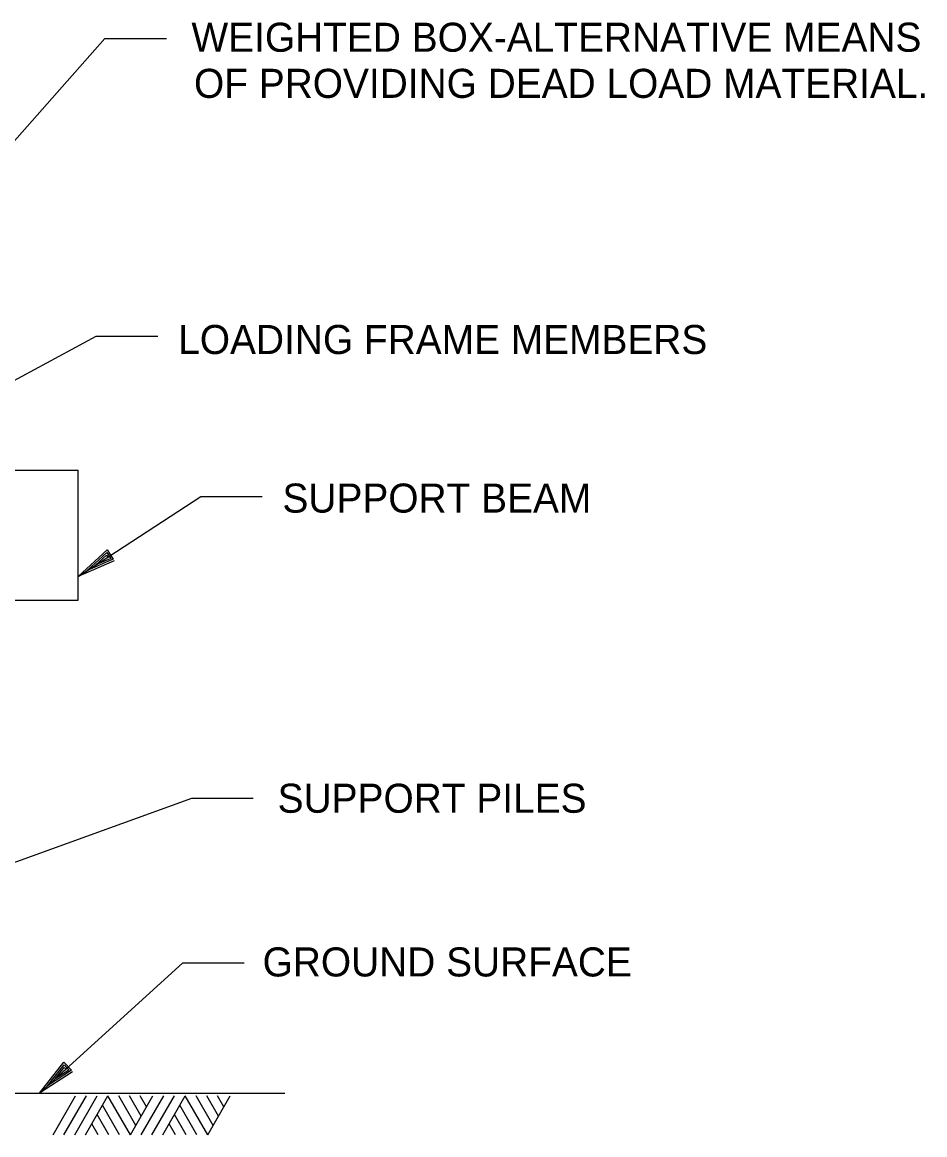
# Model space of a CAD drawing. Extents: x 22378.6 to 22422.6, y 22377.7 to 22411.7.
# Drawn here: x 22406.91 to 22411.26, y 22385.55 to 22390.91 of the extents above; entities that cross this region are included whole.
import ezdxf

# ---------------------------------------------------------------- set-up
doc = ezdxf.new("R2010")
doc.units = 0
for name, color, linetype in [('Level 1', 7, 'Continuous'), ('Level 2', 7, 'Continuous'), ('Level 4', 7, 'Continuous'), ('Level 7', 7, 'Continuous')]:
    doc.layers.add(name, color=color, linetype=linetype)

msp = doc.modelspace()

# ---------------------------------------------------------------- linework, layer by layer
at = {"layer": 'Level 1'}
for p, q in [((22407.2248, 22388.2647), (22407.2248, 22388.2647)), ((22407.1812, 22388.2362), (22407.1812, 22388.2362)), ((22406.9956, 22385.7482), (22406.9956, 22385.7482)), ((22407.0341, 22385.7832), (22407.0341, 22385.7832)), ((22407.0606, 22385.5474), (22407.1689, 22385.7349)), ((22407.1126, 22385.5474), (22407.2209, 22385.7349)), ((22407.1646, 22385.5474), (22407.2729, 22385.7349)), ((22407.2165, 22385.5474), (22407.3247, 22385.7349)), ((22407.433, 22385.5474), (22407.3247, 22385.7349)), ((22407.459, 22385.5924), (22407.3767, 22385.7349)), ((22407.485, 22385.6374), (22407.4287, 22385.7349)), ((22407.433, 22385.5474), (22407.5412, 22385.7348)), ((22407.511, 22385.6824), (22407.4807, 22385.7349)), ((22407.485, 22385.5474), (22407.5934, 22385.7349)), ((22407.5369, 22385.5474), (22407.6452, 22385.7349)), ((22407.5889, 22385.5474), (22407.6972, 22385.7349)), ((22407.8055, 22385.5474), (22407.6972, 22385.7349)), ((22407.8315, 22385.5924), (22407.7492, 22385.7349)), ((22407.8575, 22385.6374), (22407.8012, 22385.7349)), ((22407.8055, 22385.5474), (22407.9139, 22385.7349)), ((22407.8835, 22385.6824), (22407.8532, 22385.7349)), ((22407.381, 22385.5474), (22407.2987, 22385.6899)), ((22407.7535, 22385.5474), (22407.6712, 22385.6899)), ((22407.329, 22385.5474), (22407.2727, 22385.6449)), ((22407.7015, 22385.5474), (22407.6452, 22385.6449)), ((22407.2771, 22385.5474), (22407.2469, 22385.5999)), ((22407.6496, 22385.5474), (22407.6194, 22385.5999))]:
    msp.add_line(p, q, dxfattribs=at)
for points in [[(22406.6812, 22390.1173), (22407.3105, 22390.8281), (22407.6069, 22390.8281)], [(22406.4937, 22388.9771), (22407.2684, 22389.3939), (22407.5648, 22389.3939)], [(22407.1812, 22388.2362), (22407.7721, 22388.6218), (22408.0684, 22388.6218)], [(22407.3548, 22388.3125), (22407.1812, 22388.2362), (22407.3209, 22388.3644), (22407.3499, 22388.32), (22407.2248, 22388.2647), (22407.3197, 22388.3517), (22407.3382, 22388.3232), (22407.2667, 22388.292), (22407.3184, 22388.3389), (22407.3261, 22388.3272), (22407.3102, 22388.3204)], [(22405.1812, 22386.2472), (22407.7285, 22387.1692), (22408.0249, 22387.1692)], [(22406.9956, 22385.7482), (22407.685, 22386.3761), (22407.9813, 22386.3761)], [(22407.1548, 22385.8512), (22406.9956, 22385.7482), (22407.113, 22385.8971), (22407.1487, 22385.8579), (22407.0341, 22385.7832), (22407.1138, 22385.8843), (22407.1367, 22385.8591), (22407.071, 22385.8169), (22407.1147, 22385.8715), (22407.1241, 22385.8611), (22407.1095, 22385.8519)]]:
    msp.add_lwpolyline(points, dxfattribs=at)
at = {"layer": 'Level 2'}
msp.add_line((22400.0525, 22385.7482), (22408.1772, 22385.7482), dxfattribs=at)
at = {"layer": 'Level 7'}
for p, q in [((22404.1812, 22388.7482), (22407.1812, 22388.7482)), ((22407.1812, 22388.1232), (22407.1812, 22388.7482)), ((22404.1812, 22388.1232), (22407.1812, 22388.1232))]:
    msp.add_line(p, q, dxfattribs=at)

# ---------------------------------------------------------------- texts
at = {"layer": 'Level 4'}
for s, p in [('WEIGHTED BOX-ALTERNATIVE MEANS', (22407.7271, 22390.7641)), ('OF PROVIDING DEAD LOAD MATERIAL.', (22407.7393, 22390.5419)), ('LOADING FRAME MEMBERS', (22407.6632, 22389.3081)), ('SUPPORT BEAM', (22408.1654, 22388.5441)), ('SUPPORT PILES', (22408.1422, 22387.0984)), ('GROUND SURFACE', (22408.0696, 22386.3099))]:
    msp.add_text(s, height=0.14, dxfattribs=at).set_placement(p)

doc.saveas('drawing.dxf')
